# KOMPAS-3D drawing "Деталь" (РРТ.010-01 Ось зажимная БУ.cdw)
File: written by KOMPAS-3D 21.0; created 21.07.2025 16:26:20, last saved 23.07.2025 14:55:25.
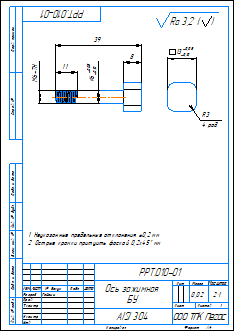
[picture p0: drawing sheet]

Sheet 1: A4, portrait

Document properties: Автор: User; Знак неуказанной шероховатости: 4; Параметр неуказанной шероховатости: Ra 3,2; Масса: 0.016583; Полное имя файла: РРТ.010 Ось зажимная БУ.m3d

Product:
- Part/product: Деталь
    Масса: 0.016583
    Форматы листов документа: A4

Title block, sheet 1: Наименование: Ось зажимная / БУ; designation: РРТ.010-01; Материал: AISI 304; Масса: 0,02; Количество листов документа: 1; organisation: ООО ТПК Пегас; Форматы листов документа: A4; stored path: C:\Users\User\Desktop\Ручной ротатор КД\Чертежи\РРТ.008 Втулка зажимная сектора.cdw; Разработал: Гайсин

Views: Вид 1, Спереди, Проекционный вид 2
Referenced files in C:\Users\User\Desktop\Ручной ротатор КД\Модели КД\: РРТ.008 Встулка зажимная.m3d, РРТ.010 Ось зажимная БУ.m3d, РРТ.008 Втулка зажима сектора.m3d
Referenced files in C:\Users\Alexey\Documents\Bitrix24\Производство\технологии\KazanTarget\эксперименты\ручной ротатор\РРТ.010-01 Ось зажимная БУ\: РРТ.010 Ось зажимная БУ.m3d
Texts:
  Ra 3,2
  Ra 3,2 ( )
  Коническая винтовая линия (Внешняя цилиндрическая ступень с метрической резьбой):1
  Эскиз выреза профиля резьбы (Внешняя цилиндрическая ступень с метрической резьбой):1
  Эскиз для винтовой линии (Внешняя цилиндрическая ступень с метрической резьбой):1
Dimensions and other numbers on the sheet: -7Н; 6; 39; 8; 11; 13; 3; 4 рад; 2:1; 1; 0,02

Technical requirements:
  Неуказанные предельные отклонения  0,2 мм
  Острые кромки притуить фаской 0,2х45  мм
